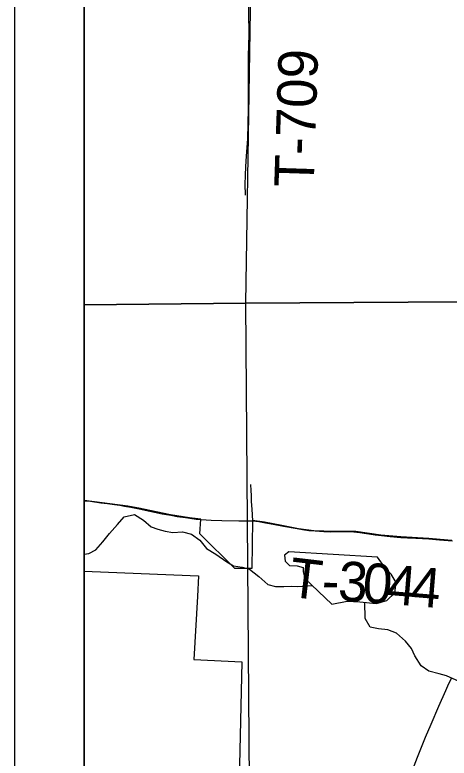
# Model space of a CAD drawing. Extents: x 0 to 34, y 0 to 22.
# Drawn here: x 1.76 to 2.385, y 15.071 to 16.14 of the extents above; entities that cross this region are included whole.
import ezdxf

# ---------------------------------------------------------------- set-up
doc = ezdxf.new("R2010")
doc.units = 0
for name, color, linetype in [('GM_X_County_Road', 7, 'Continuous'), ('GM_X_County_Road_Text', 7, 'Continuous'), ('GM_X_Interchange_Ramps', 7, 'Continuous'), ('GM_X_Minor_River_Text', 7, 'Continuous'), ('GM_X_State_Route', 7, 'Continuous'), ('GM_X_Township_Text', 7, 'Continuous'), ('SH_Data', 7, 'Continuous')]:
    doc.layers.add(name, color=color, linetype=linetype)

msp = doc.modelspace()

# ---------------------------------------------------------------- linework, layer by layer
at = {"layer": 'GM_X_County_Road'}
for points in [[(2.3805, 15.168), (2.3833, 15.1744), (2.3886, 15.1856)], [(2.3247, 15.0329), (2.3399, 15.072), (2.3515, 15.1008), (2.3595, 15.1196), (2.3705, 15.1452), (2.3805, 15.168)]]:
    msp.add_lwpolyline(points, dxfattribs=at)
at = {"layer": 'GM_X_County_Road_Text'}
for points in [[(1.8602, 15.3641), (1.8669, 15.3651), (1.8767, 15.3704), (1.887, 15.3818), (1.8964, 15.3939), (1.9078, 15.4065), (1.9176, 15.4178), (1.9324, 15.4209), (1.9453, 15.413), (1.9563, 15.4035), (1.9662, 15.4001), (1.9768, 15.3971), (1.9874, 15.3952), (2.0014, 15.396), (2.0147, 15.3926), (2.0265, 15.3843), (2.0363, 15.3721), (2.0496, 15.3638), (2.0652, 15.3528), (2.075, 15.3472), (2.0875, 15.3453)], [(2.0875, 15.3453), (2.0978, 15.3423), (2.1114, 15.3317), (2.1243, 15.3203), (2.1353, 15.3177), (2.1475, 15.3177), (2.1581, 15.3181), (2.1675, 15.3173), (2.1883, 15.3191)], [(2.4697, 15.1592), (2.4619, 15.1623), (2.4478, 15.1668), (2.438, 15.1699), (2.4262, 15.1714), (2.416, 15.1725), (2.4065, 15.1763), (2.3955, 15.1827), (2.3815, 15.1887), (2.3712, 15.1918), (2.3561, 15.1955), (2.3451, 15.2035), (2.336, 15.2175), (2.331, 15.2281), (2.3223, 15.2387), (2.3094, 15.2501), (2.2973, 15.2553), (2.2836, 15.2568), (2.2719, 15.2591), (2.2643, 15.2716), (2.2639, 15.2948)]]:
    msp.add_lwpolyline(points, dxfattribs=at)
at = {"layer": 'GM_X_Interchange_Ramps'}
for points in [[(2.0973, 16.1065), (2.0974, 16.1168), (2.0972, 16.1385), (2.0969, 16.1634), (2.0969, 16.1852), (2.0972, 16.2101), (2.0976, 16.2381), (2.0979, 16.263), (2.0988, 16.3128), (2.0993, 16.3315), (2.0995, 16.3439), (2.1, 16.3625), (2.1006, 16.381), (2.1012, 16.3965), (2.1017, 16.4121), (2.1021, 16.4308), (2.1024, 16.4463), (2.1028, 16.468), (2.1031, 16.4804), (2.1037, 16.4929), (2.1045, 16.5107)], [(2.0929, 15.9217), (2.0939, 15.9366), (2.0947, 15.949), (2.0954, 15.9614), (2.0963, 15.9832), (2.0966, 16.005), (2.0967, 16.0237), (2.0966, 16.0392), (2.0965, 16.0517), (2.0965, 16.0765), (2.0972, 16.1013), (2.0973, 16.1065)], [(2.0923, 15.8807), (2.0919, 15.8963), (2.0921, 15.9087), (2.0929, 15.9217)], [(2.1026, 15.412), (2.1017, 15.4288), (2.101, 15.4396), (2.1008, 15.4486), (2.1003, 15.4555), (2.1001, 15.4642)], [(1.8602, 15.4407), (1.8632, 15.4408), (1.8692, 15.4402), (1.8842, 15.438), (1.8935, 15.4367), (1.9035, 15.4353), (1.9114, 15.4343), (1.9179, 15.4331), (1.9272, 15.4316), (1.9392, 15.4292), (1.9543, 15.426), (1.9725, 15.4221), (1.9847, 15.42), (1.9939, 15.4184), (2.006, 15.4166), (2.012, 15.4158), (2.0211, 15.4145), (2.0283, 15.4138)], [(2.0283, 15.4138), (2.0426, 15.4128), (2.0581, 15.4123), (2.0828, 15.412), (2.1026, 15.412)], [(2.1026, 15.412), (2.1112, 15.4108), (2.1211, 15.409), (2.132, 15.4073), (2.1469, 15.4044), (2.1639, 15.4013), (2.1742, 15.3994), (2.1835, 15.3982), (2.1927, 15.3974), (2.205, 15.3965), (2.2141, 15.3961), (2.2202, 15.3964), (2.2266, 15.3964), (2.2389, 15.3965), (2.2481, 15.3963), (2.2569, 15.3953), (2.2666, 15.3938), (2.2788, 15.392), (2.288, 15.3908), (2.3004, 15.3895), (2.3159, 15.3882), (2.3252, 15.3876), (2.3376, 15.3869), (2.3562, 15.3859), (2.3717, 15.3848), (2.3903, 15.3831)]]:
    msp.add_lwpolyline(points, dxfattribs=at)
at = {"layer": 'GM_X_Minor_River_Text'}
for points in [[(2.2165, 15.292), (2.2385, 15.2966), (2.2567, 15.2955), (2.2802, 15.2932), (2.2957, 15.2971), (2.3074, 15.3084), (2.3093, 15.3232), (2.3017, 15.335), (2.2934, 15.3444), (2.2824, 15.3596), (2.1546, 15.3674), (2.1485, 15.3628), (2.1493, 15.3537), (2.1554, 15.3477), (2.1668, 15.3473), (2.1751, 15.345), (2.1751, 15.3386), (2.1778, 15.3291)], [(2.1778, 15.3291), (2.2165, 15.292)]]:
    msp.add_lwpolyline(points, dxfattribs=at)
at = {"layer": 'GM_X_State_Route'}
for points in [[(4.1201, 16.507), (4.1149, 16.7255), (3.8667, 16.7261), (3.8624, 16.726), (3.8538, 16.7259), (3.7775, 16.7251), (3.6944, 16.7259), (3.6091, 16.7254), (3.5492, 16.7252), (3.5064, 16.7242), (3.4642, 16.7247), (3.3781, 16.7258), (3.3363, 16.7271), (3.2929, 16.7282), (3.2508, 16.7281), (3.0563, 16.7255), (2.994, 16.7266), (1.8602, 16.7212), (1.8602, 14.3866), (4.1451, 14.3866)], [(2.3894, 15.3838), (2.356, 15.3864), (2.3157, 15.3888), (2.2871, 15.3914), (2.2509, 15.3968), (2.205, 15.397), (2.1906, 15.3975), (2.1685, 15.4005), (2.1447, 15.4052), (2.1196, 15.4099), (2.1024, 15.4125), (2.1014, 15.3436), (2.0771, 15.3436), (2.0265, 15.3933), (2.0281, 15.4144), (2.0118, 15.4163), (1.9845, 15.4205), (1.9386, 15.43), (1.923, 15.4329), (1.8602, 15.4414), (1.8602, 15.3394), (1.9891, 15.3342), (2.0245, 15.3327), (2.0229, 15.3029), (2.0179, 15.2125), (2.087, 15.2089), (2.0829, 15.0394)]]:
    msp.add_lwpolyline(points, dxfattribs=at)
for points in [[(1.8602, 16.7185), (1.8602, 15.723), (2.0927, 15.7254), (2.1086, 16.7183)], [(2.1086, 16.7183), (3.0962, 16.7214), (3.1048, 15.7312), (2.0927, 15.7254)], [(1.8602, 15.723), (1.8602, 14.7217), (2.1005, 14.722), (2.0927, 15.7254)], [(2.0927, 15.7254), (3.1048, 15.7312), (3.1155, 14.7229), (2.1005, 14.722)]]:
    msp.add_lwpolyline(points, close=True, dxfattribs=at)
at = {"layer": 'SH_Data'}
for points in [[(1.7602, 21.2866), (8.7602, 21.2866), (8.7602, 14.2866), (1.7602, 14.2866)], [(1.8602, 21.1866), (8.6602, 21.1866), (8.6602, 14.3866), (1.8602, 14.3866)]]:
    msp.add_lwpolyline(points, close=True, dxfattribs=at)

# ---------------------------------------------------------------- texts
at = {"layer": 'GM_X_Township_Text'}
for s, height, rotation, p in [('T-709', 0.05682, 88.1185, (2.1903, 15.8914)), ('T', 0.0568, 353.2774, (2.153, 15.3031)), ('3', 0.0568, 356.3808, (2.2244, 15.2975)), ('0', 0.0568, 355.6089, (2.2592, 15.2953)), ('4', 0.0568, 355.4001, (2.294, 15.2927)), ('4', 0.0568, 355.353, (2.3289, 15.2898)), ('-', 0.0568, 359.5082, (2.2019, 15.2977))]:
    msp.add_text(s, height=height, rotation=rotation, dxfattribs=at).set_placement(p)

doc.saveas('drawing.dxf')
